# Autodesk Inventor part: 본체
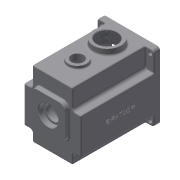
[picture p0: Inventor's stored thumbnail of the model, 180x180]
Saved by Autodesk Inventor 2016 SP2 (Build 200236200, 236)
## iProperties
Created: 2016-02
Part Number: 본체
Material: 알루미늄 6061
Document SubType Name: Modeling
Designer: mduedu
Density: 2.7 g/cm^3
Mass: 1348.73 g
Surface Area: 1142.22 cm^2
Volume: 499.531 cm^3
Appearance: 기본값
Author: mduedu
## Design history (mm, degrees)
sketch "스케치1"
  geometry: L1 (-47, -47)-(47, -47); L2 (47, -47)-(47, 63); L3 (47, 63)-(-47, 63); L4 (-47, 63)-(-47, -47); 2 further points
  constraints: 8 end point, 2 parallel, 1 horizontal, 1 midpoint, 1 perpendicular, 1 vertical alignment
  dimensions: "d0" = 94 distance of L2.end L3.end; "d155" = 110 distance of L1.end L2.end; "d156" = 47 distance from line of L1 point (0, 0)
extrude "돌출1" new body sketch "스케치1" distance "d2" = 130; taper "d3" = 0 deg
sketch "스케치3"
  geometry: C1 r 40 at (0, 0); 1 further point
  constraints: 1 centre point, 1 coincident
  dimensions: "d9" = 80 diameter of C1
extrude "돌출3" cut sketch "스케치3" distance "d11" = 121; taper "d12" = 0 deg
sketch "스케치4"
  geometry: C1 r 21 at (0, 11); 1 further point
  constraints: 1 centre point, 1 vertical alignment
  dimensions: "d13" = 21 radius of C1; "d15" = 11 distance of point (0, 0) C1.centre
extrude "돌출4" join sketch "스케치4" distance "d16" = 7; taper "d17" = 0 deg
sketch "스케치5"
  geometry: C1 r 15 at (0, -20); 1 further point
  constraints: 1 centre point, 1 vertical alignment
  dimensions: "d18" = 15 radius of C1; "d20" = 20 distance of point (0, 0) C1.centre
extrude "돌출5" join sketch "스케치5" distance "d21" = 7; taper "d22" = 0 deg
sketch "스케치6"
  geometry: L1 (-28, -17)-(28, -17); L2 (28, -17)-(28, 39); L3 (28, 39)-(-28, 39); L4 (-28, 39)-(-28, -17); L5 (-28, -17)-(28, 39); L6 (28, -17)-(-28, 39); C1 r 28 at (0, 11); A1 r 21 centre (0, 11) between (8.978, -7.984) and (-8.978, -7.984) reference; 1 further point
  constraints: 12 end point, 2 midpoint, 2 parallel, 2 tangent, 1 centre point, 1 coincident, 1 horizontal, 1 perpendicular
  dimensions: "d23" = 56 diameter of C1
extrude "돌출6" join sketch "스케치6" distance "d25" = 7; taper "d26" = -3 deg
hole "구멍1" diameter "d29" = 35; stored, may be unused: countersink angle "d33" = 90 deg, drill point angle "d35" = 0 deg; dims "d27" = 10, "d28" = 10, "d30" = 6, "d31" = 4, "d32" = 2, "d34" = 10
hole "구멍2" diameter "d38" = 22; stored, may be unused: countersink angle "d42" = 90 deg, drill point angle "d44" = 0 deg; dims "d36" = 10, "d37" = 10, "d39" = 6, "d40" = 4, "d41" = 2, "d43" = 7
hole "구멍3" diameter "d47" = 19; stored, may be unused: countersink angle "d51" = 90 deg, drill point angle "d53" = 0 deg; dims "d45" = 10, "d46" = 10, "d48" = 6, "d49" = 4, "d50" = 2, "d52" = 1
hole "구멍4" diameter "d56" = 32; stored, may be unused: countersink angle "d60" = 90 deg, drill point angle "d62" = 0 deg; dims "d57" = 6, "d58" = 4, "d59" = 2, "d61" = 8, "d220" = 10, "d221" = 10
hole "구멍5" diameter "d65" = 25; stored, may be unused: countersink angle "d69" = 90 deg, drill point angle "d71" = 0 deg; dims "d63" = 10, "d64" = 10, "d66" = 6, "d67" = 4, "d68" = 2, "d70" = 8
fillet "모깎기2" dims "d73" = 0.3
fillet "모깎기3" dims "d74" = 2
chamfer "모따기1" distance "d75" = 1; stored, may be unused: second distance "d76" = 2, angle "d77" = 45 deg
fillet "모깎기4" dims "d78" = 3
sketch "스케치16"
  geometry: L1 (-23, 32.726)-(23, 32.726); L2 (23, 32.726)-(23, 53); L3 (23, 53)-(-23, 53); L4 (-23, 53)-(-23, 32.726); L5 (-47, 63)-(47, 63) reference; 3 further points
  constraints: 8 end point, 2 parallel, 1 horizontal, 1 midpoint, 1 perpendicular, 1 vertical alignment, 2 other
  dimensions: "d160" = 46 distance of L2.end L3.end; "d163" = 10 distance between parallel lines of L3 L5
extrude "돌출15" cut sketch "스케치16" stored distance "d164" = 10; taper "d165" = 0 deg
fillet "모깎기5" dims "d79" = 2
fillet "모깎기15" dims "d166" = 5
sketch "스케치7"
  geometry: L1 (-23, 48)-(-23, 35.228) reference; L2 (23, 35.228)-(23, 48) reference; L3 (18, 53)-(-18, 53) reference; L4 (47, 63)-(47, -47) reference; L5 (47, -47)-(-47, -47) reference; L6 (-47, -47)-(-47, 63) reference; L7 (-47, 63)-(47, 63) reference; L8 (-26, 48)-(-26, 35.228); L9 (26, 35.228)-(26, 48); L10 (18, 56)-(-18, 56); C1 r 43 at (0, 0); A1 r 5 centre (-18, 48) between (-18, 53) and (-23, 48) reference; A2 r 5 centre (-28, 35.228) between (-24.889, 31.314) and (-23, 35.228) reference; A3 r 40 centre (0, 0) between (-24.889, 31.314) and (24.889, 31.314) reference; A4 r 5 centre (28, 35.228) between (23, 35.228) and (24.889, 31.314) reference; A5 r 5 centre (18, 48) between (23, 48) and (18, 53) reference; A6 r 8 centre (-18, 48) between (-18, 56) and (-26, 48); A7 r 2 centre (-28, 35.228) between (-26.756, 33.662) and (-26, 35.228); A8 r 43 centre (0, 0) between (-26.756, 33.662) and (26.756, 33.662); A9 r 2 centre (28, 35.228) between (26, 35.228) and (26.756, 33.662); A10 r 8 centre (18, 48) between (26, 48) and (18, 56); 1 further point
  constraints: 10 point on circle, 6 centre point, 6 end point, 1 coincident, 7 other
  dimensions: "d80" = 86 diameter of C1; "d167" = 3 distance between parallel lines of L3 L10
extrude "돌출7" cut sketch "스케치7" distance "d83" = 9; taper "d84" = 0 deg
sketch "스케치8" dims "d168" = 36
  geometry: L1 (-36, 4)-(-39.799, 4); L2 (-36, -4)-(-39.799, -4); A1 r 4 centre (-36, 0) between (-36, 4) and (-36, -4); A2 r 40 centre (0, 0) between (-24.889, 31.314) and (24.889, 31.314) reference; A3 r 40 centre (0, 0) between (-39.799, 4) and (-39.799, -4); 2 further points
  constraints: 5 point on circle, 4 end point, 2 centre point, 2 coincident, 2 horizontal alignment, 2 tangent, 1 horizontal, 1 parallel, 2 other
  dimensions: "d169" = 4 radius of A1
extrude "돌출9" join sketch "스케치8" stored distance "d89" = 9; taper "d90" = 0 deg
fillet "모깎기6" dims "d91" = 3.5
node "작업 평면1"
sketch "스케치9"
  geometry: L1 (47, 63)-(33, 63); L2 (33, 63)-(33, 30); L3 (33, 30)-(47, 30); L4 (47, 30)-(47, 63); L5 (47, 63)-(-47, 63) reference; L6 (47, -47)-(47, 63) reference; A1 r 40 centre (0, 0) between (-39.148, -8.214) and (39.148, -8.214) reference; 1 further point
  constraints: 8 end point, 2 parallel, 1 coincident, 1 horizontal, 1 perpendicular
  dimensions: "d95" = 33 distance from line of L2 point (0, 0); "d96" = 30 distance from line of L3 point (0, 0)
extrude "돌출10" cut sketch "스케치9" distance "d97" = 110; taper "d98" = 0 deg
extrude "돌출21" cut sketch "스케치9" stored distance "d217" = 10; taper "d218" = 0 deg
sketch "스케치11" dims "d20" = 20
  geometry: L1 (-40, -40)-(40, -40); L2 (40, -40)-(40, 56); L3 (40, 56)-(-40, 56); L4 (-40, 56)-(-40, -40); L5 (-47, -47)-(47, -47) reference; L6 (47, 63)-(-47, 63) reference; L7 (-47, 63)-(-47, -47) reference; C1 r 3.5 at (-40, 56); C2 r 3.5 at (40, 56); C3 r 3.5 at (40, -40); C4 r 3.5 at (-40, -40); 1 further point
  constraints: 8 end point, 4 centre point, 4 coincident, 3 equal radius, 2 parallel, 1 horizontal, 1 perpendicular
  dimensions: "d109" = 80 distance of L2.end L3.end; "d112" = 7 diameter of C1; "d157" = 7 distance from line of L1.start L5; "d158" = 7 distance between parallel lines of L6 L3; "d159" = 7 distance from line of L7 L3.end
extrude "돌출12" cut sketch "스케치11" stored distance "d113" = 63; taper "d114" = 0 deg
fillet "모깎기7" dims "d115" = 5, "d187" = 5
fillet "모깎기8" dims "d116" = 5
fillet "모깎기18" dims "d219" = 2
fillet "모깎기12" dims "d120" = 2
fillet "모깎기13" dims "d121" = 2
sketch "스케치12"
  geometry: 3 further points
  constraints: 2 horizontal alignment
hole "구멍6" sketch "스케치12" at (36, 0), (-36, 0) diameter "d122" = 3.242; stored, may be unused: countersink angle "d126" = 90 deg, drill point angle "d128" = 120 deg; dims "d123" = 7, "d124" = 4, "d125" = 2, "d127" = 9
fillet "모깎기14" dims "d147" = 10
chamfer "모따기4" distance "d151" = 1; stored, may be unused: second distance "d152" = 2, angle "d153" = 45 deg
sketch "스케치20"
  geometry: L1 (73, -12)-(73, -130) reference; L2 (84, -8)-(77, -8) reference; L3 (84, 0)-(84, -8) reference; L4 (84, 0)-(0, 0) reference; L5 (7, -8)-(0, -8) reference; L6 (11, -130)-(11, -12) reference; L7 (0, -8)-(0, 0) reference; L8 (73, -130)-(11, -130) reference; L9 (42, 0)-(42, -130); C1 r 10 at (42, -89); A1 r 4 centre (77, -12) between (77, -8) and (73, -12) reference; A2 r 4 centre (7, -12) between (11, -12) and (7, -8) reference
  constraints: 2 end point, 1 centre point, 1 midpoint, 1 point on line
  dimensions: "d189" = 20 diameter of C1; "d190" = 41 distance from line of C1.centre L8
extrude "돌출19" cut sketch "스케치20" stored distance "d191" = 10; taper "d192" = 0 deg
sketch "스케치18"
  geometry: C1 r 15 at (42, -89); C2 r 10 at (42, -89) reference; 1 further point
  constraints: 1 centre point, 1 concentric
  dimensions: "d174" = 30 diameter of C1
extrude "돌출17" join sketch "스케치18" distance "d175" = 5; taper "d176" = 0 deg
fillet "모깎기16" dims "d177" = 2
sketch "스케치19"
  geometry: C1 r 10 at (18, 80) reference; C2 r 15 at (18, 80); 1 further point
  constraints: 1 centre point, 1 coincident
  dimensions: "d178" = 30 diameter of C2
extrude "돌출18" cut sketch "스케치19" distance "d181" = 5; taper "d182" = 0 deg
chamfer "모따기5" distance "d183" = 0.5; stored, may be unused: second distance "d184" = 2, angle "d185" = 45 deg
sketch "스케치21"
  geometry: L1 (-12, 14)-(-130, 14) reference; L2 (-8, 0)-(-8, 10) reference; L3 (0, 0)-(0, 100) reference; L4 (-8, 100)-(0, 100) reference; L5 (-8, 74)-(-8, 100) reference; L6 (-130, 70)-(-12, 70) reference; L7 (-130, 14)-(-130, 70) reference; L8 (0, 0)-(-8, 0) reference; L9 (-130, 14)-(-130, 70) reference; L10 (27.4, 42)-(-164.4, 42) reference; A1 r 4 centre (-12, 74) between (-12, 70) and (-8, 74) reference; A2 r 4 centre (-12, 10) between (-8, 10) and (-12, 14) reference; 3 further points
  constraints: 1 coincident, 1 point on line, 1 other
  dimensions: "d222" = 65 distance from line of point (-65, 42) L9
feature "엠보싱2" sketch "스케치21" dims "d20" = 20, "d193" = 0.5, "d194" = 0
sketch "스케치22"
  geometry: L1 (73, -12)-(73, -130) reference; L2 (84, -8)-(77, -8) reference; L3 (84, 0)-(84, -8) reference; L4 (84, 0)-(0, 0) reference; L5 (7, -8)-(0, -8) reference; L6 (11, -130)-(11, -12) reference; L7 (0, -8)-(0, 0) reference; L8 (73, -130)-(11, -130) reference; L9 (42, -130)-(42, 0); C1 r 17 at (42, -89) reference; C2 r 22.5 at (42, -40); A1 r 4 centre (77, -12) between (77, -8) and (73, -12) reference; A2 r 4 centre (7, -12) between (11, -12) and (7, -8) reference
  constraints: 2 end point, 1 centre point, 1 midpoint, 1 point on line
  dimensions: "d195" = 45 diameter of C2; "d197" = 40 distance from line of C2.centre L4
extrude "돌출20" join sketch "스케치22" distance "d198" = 10; taper "d199" = 0 deg
fillet "모깎기17" dims "d200" = 3
hole "구멍7" diameter "d203" = 33.376; stored, may be unused: countersink angle "d207" = 90 deg, drill point angle "d209" = 118 deg; dims "d204" = 6, "d205" = 4, "d206" = 2, "d208" = 8, "d223" = 10, "d224" = 10
chamfer "모따기6" distance "d210" = 1; stored, may be unused: second distance "d211" = 2, angle "d212" = 45 deg
fillet "모깎기19" dims "d225" = 2
node "솔리드1"
pattern_circular "원형 패턴1" dims angle "d93" = 360 deg
mirror "대칭1"
mirror "대칭2"
node "투영된 루프1"
node "투영된 루프2"
node "투영된 루프3"
node "절단 모서리 투영3"
